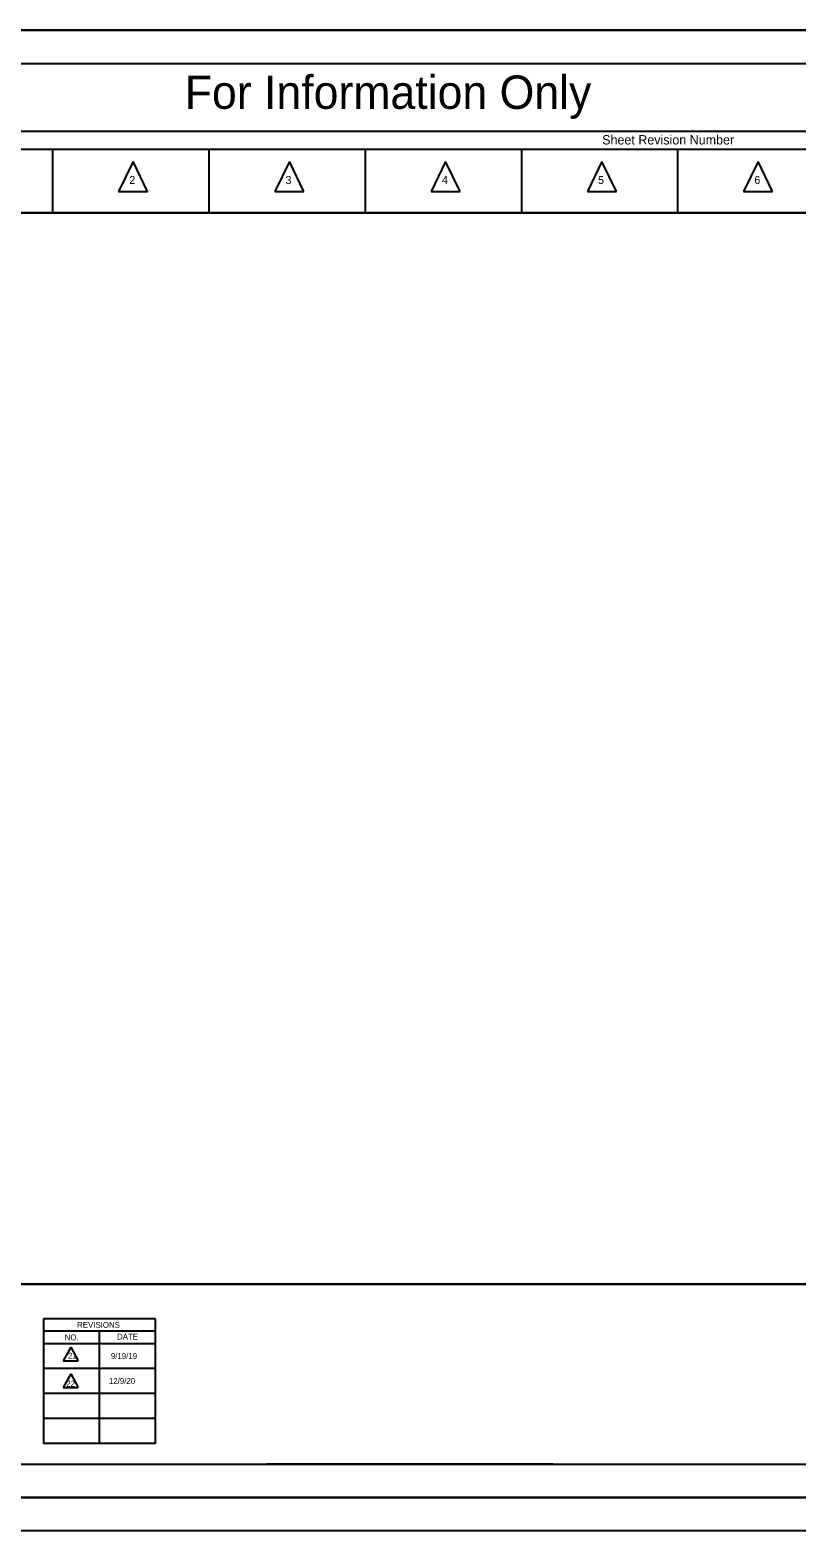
# Model space of a CAD drawing. Extents: x -2251 to 10196, y -13470 to 1199.
# Drawn here: x 5659 to 6234, y -8951 to -7826 of the extents above; entities that cross this region are included whole.
import ezdxf

# ---------------------------------------------------------------- set-up
doc = ezdxf.new("R2010")
doc.units = 0
for name, color, linetype in [('RD_SHT_Bndy', 7, 'Continuous'), ('RD_SHT_Iplotshp', 7, 'Continuous'), ('RD_SHT_Misc1', 7, 'Continuous'), ('RD_SHT_Snap', 7, 'Continuous'), ('RD_SHT_TX', 7, 'Continuous'), ('RD_TX_RoadID', 7, 'Continuous')]:
    doc.layers.add(name, color=color, linetype=linetype)

msp = doc.modelspace()

# ---------------------------------------------------------------- linework, layer by layer
at = {"layer": 'RD_SHT_Bndy'}
for p, q in [((6791.6, -7825.6), (5031.6, -7825.6)), ((5103.1, -7850.6), (6778.1, -7850.6)), ((5153.4, -7914.8), (6731.1, -7914.8)), ((5676, -7962.6), (5676, -7914.8)), ((5793.1, -7962.6), (5793.1, -7914.8)), ((5910.2, -7962.6), (5910.2, -7914.8)), ((6027.3, -7962.6), (6027.3, -7914.8)), ((6144.3, -7962.6), (6144.3, -7914.8)), ((5736.2, -7924.1), (5725.2, -7946.6)), ((5746.9, -7946.6), (5736.2, -7924.1)), ((5853.2, -7924.1), (5842.3, -7946.6)), ((5864, -7946.6), (5853.2, -7924.1)), ((5970.3, -7924.1), (5959.4, -7946.6)), ((5981.1, -7946.6), (5970.3, -7924.1)), ((6087.4, -7924.1), (6076.5, -7946.6)), ((6098.2, -7946.6), (6087.4, -7924.1)), ((6204.5, -7924.1), (6193.5, -7946.6)), ((6215.3, -7946.6), (6204.5, -7924.1)), ((5725.2, -7946.6), (5746.9, -7946.6)), ((5842.3, -7946.6), (5864, -7946.6)), ((5959.4, -7946.6), (5981.1, -7946.6)), ((6076.5, -7946.6), (6098.2, -7946.6)), ((6193.5, -7946.6), (6215.3, -7946.6)), ((5153.4, -7962.6), (6731.1, -7962.6)), ((5103.1, -8900.6), (6778.1, -8900.6)), ((6050.9, -8900.6), (5836.1, -8900.6)), ((6791.6, -8925.6), (5031.6, -8925.6)), ((6791.6, -8950.7), (5031.6, -8950.6))]:
    msp.add_line(p, q, dxfattribs=at)
msp.add_lwpolyline([(5153.4, -7901.3), (6731.1, -7901.3), (6731.1, -8765.6), (5153.4, -8765.6)], close=True, dxfattribs=at)
at = {"layer": 'RD_SHT_Iplotshp'}
msp.add_lwpolyline([(4996.6, -7825.6), (6796.6, -7825.6), (6796.6, -8925.6), (4996.6, -8925.6)], close=True, dxfattribs=at)
at = {"layer": 'RD_SHT_Misc1'}
msp.add_lwpolyline([(6796.6, -8925.6), (6796.7, -7825.6), (5096.7, -7825.6), (5096.6, -8925.6)], close=True, dxfattribs=at)
at = {"layer": 'RD_SHT_Snap'}
msp.add_lwpolyline([(5008.1, -7825.6), (6808.1, -7825.6), (6808.1, -8925.6), (5008.1, -8925.6)], close=True, dxfattribs=at)
at = {"layer": 'RD_SHT_TX'}
for p, q in [((5752.9, -8791.6), (5668.9, -8791.6)), ((5668.9, -8791.6), (5668.9, -8885.1)), ((5752.9, -8885.1), (5752.9, -8791.6)), ((5752.9, -8800.9), (5668.9, -8800.9)), ((5710.9, -8885.1), (5710.9, -8800.9)), ((5752.9, -8810.3), (5668.9, -8810.3)), ((5689.4, -8813), (5683.7, -8823.2)), ((5689.4, -8813), (5695.1, -8823.2)), ((5752.9, -8829), (5668.9, -8829)), ((5683.7, -8823.2), (5695.1, -8823.2)), ((5689.4, -8832.9), (5683.7, -8843.1)), ((5683.7, -8843.1), (5695.1, -8843.1)), ((5689.4, -8832.9), (5695.1, -8843.1)), ((5752.9, -8847.7), (5668.9, -8847.7)), ((5752.9, -8866.4), (5668.9, -8866.4)), ((5752.9, -8885.1), (5668.9, -8885.1))]:
    msp.add_line(p, q, dxfattribs=at)
at = {"layer": 'RD_TX_RoadID'}
msp.add_lwpolyline([(5150.5, -8765.7), (6733.9, -8765.7), (6733.9, -7962.6), (5150.5, -7962.6)], close=True, dxfattribs=at)

# ---------------------------------------------------------------- texts
at = {"layer": 'RD_SHT_Bndy'}
for s, height, p in [('Sheet Revision Number', 7, (6087.6, -7911.4)), ('2', 6, (5733.3, -7941)), ('3', 6, (5850.3, -7941)), ('4', 6, (5967.5, -7941)), ('5', 6, (6084.5, -7941)), ('6', 6, (6201.6, -7941))]:
    msp.add_text(s, height=height, dxfattribs=at).set_placement(p)
at = {"layer": 'RD_SHT_TX'}
for s, height, p in [('For Information Only', 25, (5774.8, -7884.7)), ('21', 4.4, (5687.4, -8821.5)), ('9/19/19', 4.4, (5719.5, -8821.7)), ('22', 4.4, (5686.1, -8842.4)), ('12/9/20', 4.4, (5718, -8840.4))]:
    msp.add_text(s, height=height, dxfattribs=at).set_placement(p)
for s, height, rotation, p in [('REVISIONS', 4.4, 360, (5694.2, -8798.4)), ('NO.', 4.4, 360, (5684.9, -8807.8)), ('DATE', 4.41, 359.7246, (5724.1, -8807.2))]:
    msp.add_text(s, height=height, rotation=rotation, dxfattribs=at).set_placement(p)

doc.saveas('drawing.dxf')
